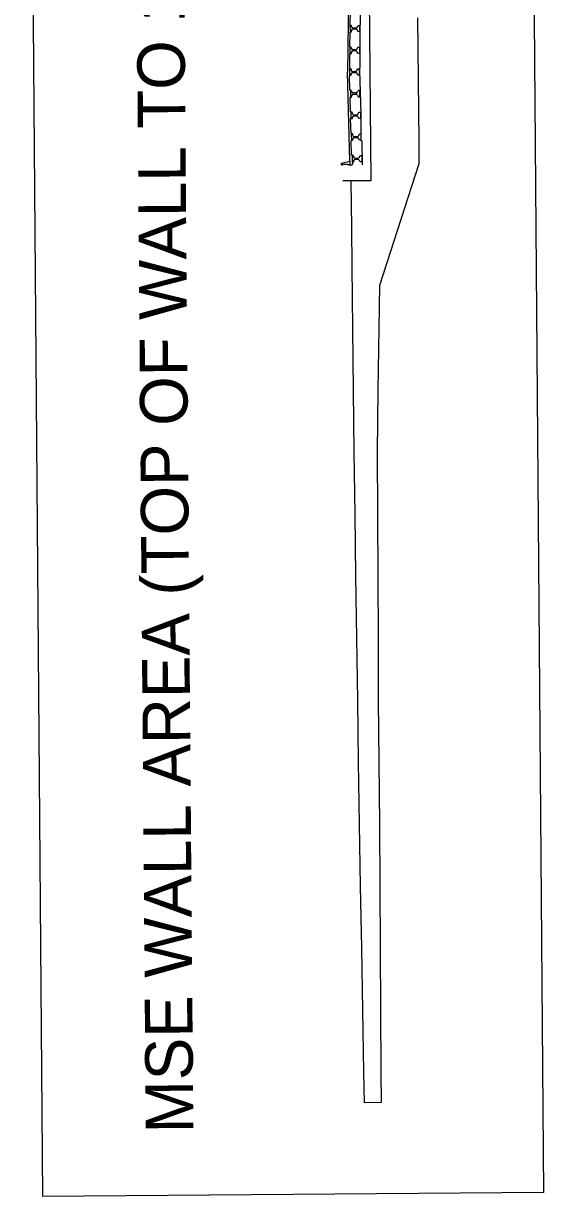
# Model space of a CAD drawing. Extents: x 592274 to 721355, y 141734 to 173089.
# Drawn here: x 594004.6 to 594214.4, y 172097.8 to 172570.9 of the extents above; entities that cross this region are included whole.
import ezdxf

# ---------------------------------------------------------------- set-up
doc = ezdxf.new("R2010")
doc.units = 0
doc.layers.add('B_CONC', color=7, linetype='Continuous')
doc.layers.add('B_SCREEN', color=7, linetype='Continuous')

msp = doc.modelspace()

# ---------------------------------------------------------------- linework, layer by layer
at = {"layer": 'B_CONC'}
for p, q in [((594144.78, 172507.62), (594143.46, 172673.56)), ((594163.48, 172573.14), (594163.78, 172548.14)), ((594163.78, 172548.14), (594164, 172523.14)), ((594164, 172523.14), (594164.07, 172514.3)), ((594164.07, 172514.3), (594148.14, 172465.2)), ((594133.34, 172507.53), (594144.78, 172507.62)), ((594148.14, 172465.2), (594147.88, 172447.97)), ((594147.88, 172447.98), (594147.56, 172422.97)), ((594147.56, 172422.98), (594147.31, 172397.98)), ((594147.31, 172397.98), (594147.39, 172372.99)), ((594147.39, 172373), (594147.58, 172348)), ((594147.58, 172348), (594147.68, 172323)), ((594147.68, 172322.99), (594147.7, 172297.99)), ((594147.7, 172298), (594147.86, 172273)), ((594147.86, 172273.01), (594148.15, 172248.01)), ((594148.15, 172248), (594148.34, 172223)), ((594148.34, 172223), (594148.42, 172198)), ((594148.42, 172198), (594148.57, 172173)), ((594148.57, 172173), (594148.7, 172148)), ((594148.7, 172148.01), (594148.83, 172135.66)), ((594148.83, 172135.66), (594142.16, 172135.61))]:
    msp.add_line(p, q, dxfattribs=at)
msp.add_lwpolyline([(594012.37, 172097.79), (594004.59, 173078.9), (594206.58, 173080.5), (594214.36, 172099.39)], close=True, dxfattribs=at)
for points in [[(594136.89, 172497.92), (594136.8, 172507.56)], [(594136.99, 172488.56), (594136.89, 172497.92)], [(594137.15, 172472.92), (594136.99, 172488.56)], [(594137.42, 172447.92), (594137.15, 172472.92)], [(594137.71, 172422.93), (594137.42, 172447.92)], [(594138.02, 172397.93), (594137.71, 172422.93)], [(594138.34, 172372.93), (594138.02, 172397.93)], [(594138.67, 172347.93), (594138.34, 172372.93)], [(594139.03, 172322.93), (594138.67, 172347.93)], [(594139.39, 172297.93), (594139.03, 172322.93)], [(594139.78, 172272.94), (594139.39, 172297.93)], [(594140.18, 172247.94), (594139.78, 172272.94)], [(594140.59, 172222.94), (594140.18, 172247.94)], [(594141.02, 172197.94), (594140.59, 172222.94)], [(594141.47, 172172.95), (594141.02, 172197.94)], [(594141.93, 172147.95), (594141.47, 172172.95)], [(594142.16, 172135.61), (594141.93, 172147.95)]]:
    msp.add_lwpolyline(points, dxfattribs=at)
at = {"layer": 'B_SCREEN'}
for p, q in [((594135.71, 172587.29), (594135.27, 172551.29)), ((594140.37, 172579.08), (594140.44, 172570.33)), ((594136.32, 172576.13), (594136.25, 172570.21)), ((594136.22, 172567.38), (594136.14, 172561.46)), ((594136.43, 172567.38), (594136.22, 172567.38)), ((594136.43, 172567.38), (594136.24, 172567.38)), ((594136.41, 172570.21), (594136.25, 172570.21)), ((594136.41, 172570.21), (594136.73, 172570.22)), ((594136.41, 172570.21), (594136.73, 172570.22)), ((594136.43, 172567.38), (594136.41, 172570.21)), ((594136.75, 172567.38), (594136.43, 172567.38)), ((594136.75, 172567.38), (594136.43, 172567.38)), ((594136.73, 172570.22), (594136.8, 172569.66)), ((594136.73, 172570.22), (594136.8, 172569.66)), ((594136.81, 172567.94), (594136.75, 172567.38)), ((594136.81, 172567.94), (594136.75, 172567.38)), ((594137.47, 172569.08), (594138.66, 172569.09)), ((594137.47, 172569.08), (594138.66, 172569.09)), ((594138.66, 172568.54), (594137.47, 172568.53)), ((594138.66, 172568.54), (594137.47, 172568.53)), ((594139.26, 172569.47), (594139.53, 172570.07)), ((594139.26, 172569.47), (594139.53, 172570.07)), ((594139.55, 172567.57), (594139.27, 172568.16)), ((594139.55, 172567.57), (594139.27, 172568.16)), ((594139.53, 172570.07), (594140.1, 172570.08)), ((594139.53, 172570.07), (594140.1, 172570.08)), ((594140.12, 172567.58), (594139.55, 172567.57)), ((594140.12, 172567.58), (594139.55, 172567.57)), ((594140.1, 172570.08), (594140.16, 172570.01)), ((594140.1, 172570.08), (594140.16, 172570.01)), ((594140.12, 172567.58), (594140.18, 172567.64)), ((594140.12, 172567.58), (594140.18, 172567.64)), ((594140.16, 172570.01), (594140.18, 172567.64)), ((594140.16, 172570.01), (594140.18, 172567.64)), ((594140.37, 172570.33), (594140.24, 172570.33)), ((594140.44, 172570.33), (594140.24, 172570.33)), ((594140.24, 172570.33), (594140.31, 172561.58)), ((594136.11, 172558.63), (594136.04, 172552.71)), ((594136.39, 172558.63), (594136.11, 172558.63)), ((594136.37, 172561.46), (594136.14, 172561.46)), ((594136.37, 172561.46), (594136.69, 172561.47)), ((594136.37, 172561.46), (594136.69, 172561.47)), ((594136.39, 172558.63), (594136.37, 172561.46)), ((594136.71, 172558.63), (594136.39, 172558.63)), ((594136.71, 172558.63), (594136.39, 172558.63)), ((594136.69, 172561.47), (594136.76, 172560.91)), ((594136.69, 172561.47), (594136.76, 172560.91)), ((594136.77, 172559.19), (594136.71, 172558.63)), ((594136.77, 172559.19), (594136.71, 172558.63)), ((594137.42, 172560.33), (594138.62, 172560.33)), ((594137.42, 172560.33), (594138.62, 172560.33)), ((594138.62, 172559.79), (594137.43, 172559.78)), ((594138.62, 172559.79), (594137.43, 172559.78)), ((594139.22, 172560.72), (594139.49, 172561.32)), ((594139.22, 172560.72), (594139.49, 172561.32)), ((594139.51, 172558.82), (594139.23, 172559.41)), ((594139.51, 172558.82), (594139.23, 172559.41)), ((594139.49, 172561.32), (594140.06, 172561.33)), ((594139.49, 172561.32), (594140.06, 172561.33)), ((594140.08, 172558.83), (594139.51, 172558.82)), ((594140.08, 172558.83), (594139.51, 172558.82)), ((594140.06, 172561.33), (594140.12, 172561.26)), ((594140.06, 172561.33), (594140.12, 172561.26)), ((594140.08, 172558.83), (594140.14, 172558.89)), ((594140.08, 172558.83), (594140.14, 172558.89)), ((594140.12, 172561.26), (594140.14, 172558.89)), ((594140.12, 172561.26), (594140.14, 172558.89)), ((594140.31, 172561.58), (594140.2, 172561.58)), ((594140.2, 172561.58), (594140.27, 172552.83)), ((594136.28, 172515.29), (594135.27, 172551.29)), ((594136.26, 172552.71), (594136.04, 172552.71)), ((594136.23, 172543.99), (594136.06, 172549.88)), ((594136.28, 172549.88), (594136.06, 172549.88)), ((594136.26, 172552.71), (594136.58, 172552.71)), ((594136.28, 172549.88), (594136.26, 172552.71)), ((594136.26, 172552.71), (594136.58, 172552.71)), ((594136.6, 172549.88), (594136.28, 172549.88)), ((594136.6, 172549.88), (594136.28, 172549.88)), ((594136.58, 172552.71), (594136.65, 172552.16)), ((594136.58, 172552.71), (594136.65, 172552.16)), ((594136.67, 172550.44), (594136.6, 172549.88)), ((594136.67, 172550.44), (594136.6, 172549.88)), ((594137.32, 172551.57), (594138.51, 172551.58)), ((594137.32, 172551.57), (594138.51, 172551.58)), ((594138.52, 172551.04), (594137.32, 172551.03)), ((594138.52, 172551.04), (594137.32, 172551.03)), ((594139.11, 172551.97), (594139.39, 172552.57)), ((594139.11, 172551.97), (594139.39, 172552.57)), ((594139.41, 172550.07), (594139.12, 172550.66)), ((594139.41, 172550.07), (594139.12, 172550.66)), ((594139.39, 172552.57), (594139.95, 172552.57)), ((594139.39, 172552.57), (594139.95, 172552.57)), ((594139.97, 172550.07), (594139.41, 172550.07)), ((594139.97, 172550.07), (594139.41, 172550.07)), ((594139.95, 172552.57), (594140.01, 172552.51)), ((594139.95, 172552.57), (594140.01, 172552.51)), ((594139.97, 172550.07), (594140.03, 172550.14)), ((594139.97, 172550.07), (594140.03, 172550.14)), ((594140.01, 172552.51), (594140.03, 172550.14)), ((594140.01, 172552.51), (594140.03, 172550.14)), ((594140.09, 172552.83), (594140.12, 172549.83)), ((594140.27, 172552.83), (594140.09, 172552.83)), ((594140.29, 172549.83), (594140.12, 172549.83)), ((594140.29, 172549.83), (594140.36, 172541.08)), ((594136.5, 172543.99), (594136.23, 172543.99)), ((594136.82, 172544), (594136.5, 172543.99)), ((594136.82, 172544), (594136.5, 172543.99)), ((594136.5, 172543.99), (594136.53, 172541.16)), ((594136.9, 172543.44), (594136.82, 172544)), ((594136.9, 172543.44), (594136.82, 172544)), ((594139.63, 172543.85), (594139.36, 172543.25)), ((594139.63, 172543.85), (594139.36, 172543.25)), ((594140.19, 172543.86), (594139.63, 172543.85)), ((594140.19, 172543.86), (594139.63, 172543.85)), ((594140.19, 172543.86), (594140.26, 172543.79)), ((594140.19, 172543.86), (594140.26, 172543.79)), ((594140.27, 172541.42), (594140.26, 172543.79)), ((594140.27, 172541.42), (594140.26, 172543.79)), ((594136.47, 172535.21), (594136.3, 172541.16)), ((594136.53, 172541.16), (594136.3, 172541.16)), ((594136.53, 172541.16), (594136.85, 172541.16)), ((594136.53, 172541.16), (594136.85, 172541.16)), ((594136.85, 172541.16), (594136.91, 172541.72)), ((594136.85, 172541.16), (594136.91, 172541.72)), ((594138.76, 172542.87), (594137.56, 172542.86)), ((594138.76, 172542.87), (594137.56, 172542.86)), ((594137.57, 172542.31), (594138.76, 172542.32)), ((594137.57, 172542.31), (594138.76, 172542.32)), ((594139.37, 172541.94), (594139.65, 172541.35)), ((594139.37, 172541.94), (594139.65, 172541.35)), ((594139.65, 172541.35), (594140.21, 172541.36)), ((594139.65, 172541.35), (594140.21, 172541.36)), ((594140.21, 172541.36), (594140.27, 172541.42)), ((594140.21, 172541.36), (594140.27, 172541.42)), ((594140.56, 172541.08), (594140.36, 172541.08)), ((594140.56, 172541.08), (594140.63, 172532.33)), ((594136.77, 172535.22), (594136.47, 172535.21)), ((594136.79, 172532.38), (594136.77, 172535.22)), ((594136.77, 172535.22), (594137.09, 172535.22)), ((594136.79, 172532.38), (594136.77, 172535.22)), ((594136.77, 172535.22), (594137.09, 172535.22)), ((594137.09, 172535.22), (594137.16, 172534.66)), ((594137.09, 172535.22), (594137.16, 172534.66)), ((594137.83, 172534.08), (594139.02, 172534.09)), ((594137.83, 172534.08), (594139.02, 172534.09)), ((594139.62, 172534.48), (594139.9, 172535.07)), ((594139.62, 172534.48), (594139.9, 172535.07)), ((594139.9, 172535.07), (594140.46, 172535.08)), ((594139.9, 172535.07), (594140.46, 172535.08)), ((594140.46, 172535.08), (594140.52, 172535.02)), ((594140.46, 172535.08), (594140.52, 172535.02)), ((594140.52, 172535.02), (594140.54, 172532.64)), ((594140.52, 172535.02), (594140.54, 172532.64)), ((594136.71, 172526.46), (594136.55, 172532.38)), ((594136.79, 172532.38), (594136.55, 172532.38)), ((594137.11, 172532.38), (594136.79, 172532.38)), ((594137.11, 172532.38), (594136.79, 172532.38)), ((594137.18, 172532.94), (594137.11, 172532.38)), ((594137.18, 172532.94), (594137.11, 172532.38)), ((594139.03, 172533.55), (594137.83, 172533.54)), ((594139.03, 172533.55), (594137.83, 172533.54)), ((594139.92, 172532.57), (594139.63, 172533.17)), ((594139.92, 172532.57), (594139.63, 172533.17)), ((594140.48, 172532.58), (594139.92, 172532.57)), ((594140.48, 172532.58), (594139.92, 172532.57)), ((594140.48, 172532.58), (594140.54, 172532.64)), ((594140.48, 172532.58), (594140.54, 172532.64)), ((594140.71, 172532.33), (594140.63, 172532.33)), ((594140.74, 172532.33), (594140.63, 172532.33)), ((594140.81, 172523.58), (594140.74, 172532.33)), ((594136.95, 172526.47), (594136.71, 172526.46)), ((594136.95, 172526.47), (594137.27, 172526.47)), ((594136.97, 172523.63), (594136.95, 172526.47)), ((594136.95, 172526.47), (594137.27, 172526.47)), ((594137.27, 172526.47), (594137.34, 172525.91)), ((594137.27, 172526.47), (594137.34, 172525.91)), ((594138.01, 172525.33), (594139.2, 172525.34)), ((594138.01, 172525.33), (594139.2, 172525.34)), ((594139.21, 172524.8), (594138.01, 172524.79)), ((594139.21, 172524.8), (594138.01, 172524.79)), ((594139.8, 172525.73), (594140.08, 172526.32)), ((594139.8, 172525.73), (594140.08, 172526.32)), ((594140.08, 172526.32), (594140.64, 172526.33)), ((594140.08, 172526.32), (594140.64, 172526.33)), ((594140.64, 172526.33), (594140.7, 172526.27)), ((594140.64, 172526.33), (594140.7, 172526.27)), ((594140.7, 172526.27), (594140.72, 172523.89)), ((594140.7, 172526.27), (594140.72, 172523.89)), ((594136.96, 172517.72), (594136.79, 172523.63)), ((594136.97, 172523.63), (594136.79, 172523.63)), ((594137.29, 172523.64), (594136.97, 172523.63)), ((594137.29, 172523.64), (594136.97, 172523.63)), ((594137.36, 172524.19), (594137.29, 172523.64)), ((594137.36, 172524.19), (594137.29, 172523.64)), ((594140.1, 172523.82), (594139.81, 172524.42)), ((594140.1, 172523.82), (594139.81, 172524.42)), ((594140.66, 172523.83), (594140.1, 172523.82)), ((594140.66, 172523.83), (594140.1, 172523.82)), ((594140.66, 172523.83), (594140.72, 172523.89)), ((594140.66, 172523.83), (594140.72, 172523.89)), ((594140.98, 172523.58), (594140.81, 172523.58)), ((594141.09, 172523.58), (594140.81, 172523.58)), ((594141.09, 172523.58), (594141.17, 172513.88)), ((594132.88, 172514.58), (594136.28, 172515.29)), ((594136.28, 172515.07), (594136.27, 172515.05)), ((594136.28, 172515.07), (594136.27, 172515.05)), ((594136.28, 172515.29), (594136.28, 172515.12)), ((594136.28, 172515.29), (594136.28, 172515.12)), ((594136.28, 172515.12), (594136.28, 172515.07)), ((594136.28, 172515.12), (594136.28, 172515.07)), ((594137.3, 172517.72), (594136.96, 172517.72)), ((594137.3, 172517.72), (594137.62, 172517.72)), ((594137.32, 172514.89), (594137.3, 172517.72)), ((594137.3, 172517.72), (594137.62, 172517.72)), ((594137.62, 172517.72), (594137.69, 172517.16)), ((594137.62, 172517.72), (594137.69, 172517.16)), ((594137.71, 172515.45), (594137.64, 172514.89)), ((594137.71, 172515.45), (594137.64, 172514.89)), ((594138.36, 172516.58), (594139.55, 172516.59)), ((594138.36, 172516.58), (594139.55, 172516.59)), ((594139.56, 172516.05), (594138.37, 172516.04)), ((594139.56, 172516.05), (594138.37, 172516.04)), ((594140.15, 172516.98), (594140.43, 172517.58)), ((594140.15, 172516.98), (594140.43, 172517.58)), ((594140.45, 172515.08), (594140.17, 172515.67)), ((594140.45, 172515.08), (594140.17, 172515.67)), ((594140.43, 172517.58), (594140.99, 172517.58)), ((594140.43, 172517.58), (594140.99, 172517.58)), ((594141.01, 172515.08), (594140.45, 172515.08)), ((594141.01, 172515.08), (594140.45, 172515.08)), ((594140.99, 172517.58), (594141.05, 172517.52)), ((594140.99, 172517.58), (594141.05, 172517.52)), ((594141.01, 172515.08), (594141.07, 172515.14)), ((594141.01, 172515.08), (594141.07, 172515.14)), ((594141.05, 172517.52), (594141.07, 172515.14)), ((594141.05, 172517.52), (594141.07, 172515.14)), ((594132.88, 172514.58), (594132.82, 172514.51)), ((594132.82, 172513.88), (594132.82, 172514.51)), ((594132.89, 172513.82), (594132.82, 172513.88)), ((594132.89, 172513.82), (594133.32, 172513.82)), ((594133.32, 172513.82), (594133.45, 172513.95)), ((594135.54, 172513.96), (594133.45, 172513.95)), ((594135.67, 172513.84), (594135.54, 172513.96)), ((594135.67, 172513.84), (594136.27, 172513.85)), ((594136.27, 172515.02), (594136.24, 172514.96)), ((594136.27, 172515.02), (594136.24, 172514.96)), ((594136.24, 172514.96), (594136.25, 172514.89)), ((594136.24, 172514.96), (594136.25, 172514.89)), ((594136.25, 172514.89), (594136.24, 172514.83)), ((594136.25, 172514.89), (594136.24, 172514.83)), ((594136.24, 172514.83), (594136.25, 172514.75)), ((594136.24, 172514.83), (594136.25, 172514.75)), ((594136.25, 172514.75), (594136.25, 172514.68)), ((594136.25, 172514.75), (594136.25, 172514.68)), ((594136.25, 172514.68), (594136.25, 172514.56)), ((594136.25, 172514.68), (594136.25, 172514.56)), ((594136.25, 172514.56), (594136.25, 172514.5)), ((594136.25, 172514.56), (594136.25, 172514.5)), ((594136.25, 172514.5), (594136.25, 172514.41)), ((594136.25, 172514.5), (594136.25, 172514.41)), ((594136.25, 172514.41), (594136.25, 172514.38)), ((594136.25, 172514.41), (594136.25, 172514.38)), ((594136.25, 172514.38), (594136.25, 172514.33)), ((594136.25, 172514.38), (594136.25, 172514.33)), ((594136.25, 172514.33), (594136.27, 172514.26)), ((594136.25, 172514.33), (594136.27, 172514.26)), ((594136.27, 172515.05), (594136.27, 172515.02)), ((594136.27, 172515.05), (594136.27, 172515.02)), ((594136.27, 172514.26), (594136.28, 172514.18)), ((594136.27, 172514.26), (594136.28, 172514.18)), ((594136.33, 172513.91), (594136.27, 172513.85)), ((594136.28, 172514.18), (594136.3, 172514.16)), ((594136.28, 172514.18), (594136.3, 172514.16)), ((594136.3, 172514.16), (594136.33, 172514.12)), ((594136.3, 172514.16), (594136.33, 172514.12)), ((594136.33, 172513.98), (594136.33, 172514.12)), ((594136.33, 172513.98), (594136.33, 172514.12)), ((594136.33, 172514.05), (594136.33, 172513.91)), ((594136.33, 172514.05), (594136.33, 172513.91)), ((594136.4, 172513.85), (594136.33, 172513.91)), ((594136.4, 172513.85), (594137.11, 172513.85)), ((594137.18, 172513.91), (594137.11, 172513.85)), ((594137.24, 172514.25), (594137.18, 172513.91)), ((594137.37, 172514.89), (594137.26, 172514.36)), ((594137.64, 172514.89), (594137.32, 172514.89)), ((594137.64, 172514.89), (594137.32, 172514.89))]:
    msp.add_line(p, q, dxfattribs=at)
msp.add_lwpolyline([(594137.24, 172514.25), (594137.17, 172514.32), (594137.26, 172514.36)], dxfattribs=at)
for centre, start, end in [((594137.46, 172569.74), 187.3266, 270.4539), ((594137.46, 172569.74), 187.3266, 270.4539), ((594137.48, 172567.87), 90.4539, 173.5812), ((594137.48, 172567.87), 90.4539, 173.5812), ((594138.65, 172569.75), 270.4539, 335.3703), ((594138.65, 172569.75), 270.4539, 335.3703), ((594138.67, 172567.88), 25.5375, 90.4539), ((594138.67, 172567.88), 25.5375, 90.4539), ((594137.42, 172560.99), 187.3266, 270.4539), ((594137.42, 172560.99), 187.3266, 270.4539), ((594137.43, 172559.12), 90.4539, 173.5812), ((594137.43, 172559.12), 90.4539, 173.5812), ((594138.61, 172561), 270.4539, 335.3703), ((594138.61, 172561), 270.4539, 335.3703), ((594138.63, 172559.13), 25.5375, 90.4539), ((594138.63, 172559.13), 25.5375, 90.4539), ((594137.31, 172552.24), 187.3266, 270.4539), ((594137.31, 172552.24), 187.3266, 270.4539), ((594137.33, 172550.37), 90.4539, 173.5812), ((594137.33, 172550.37), 90.4539, 173.5812), ((594138.51, 172552.25), 270.4539, 335.3703), ((594138.51, 172552.25), 270.4539, 335.3703), ((594138.52, 172550.37), 25.5375, 90.4539), ((594138.52, 172550.37), 25.5375, 90.4539), ((594137.56, 172543.52), 187.3266, 270.4539), ((594137.56, 172543.52), 187.3266, 270.4539), ((594137.57, 172541.65), 90.4539, 173.5812), ((594137.57, 172541.65), 90.4539, 173.5812), ((594138.75, 172543.53), 270.4539, 335.3703), ((594138.75, 172543.53), 270.4539, 335.3703), ((594138.77, 172541.66), 25.5375, 90.4539), ((594138.77, 172541.66), 25.5375, 90.4539), ((594137.82, 172534.74), 187.3266, 270.4539), ((594137.82, 172534.74), 187.3266, 270.4539), ((594139.02, 172534.75), 270.4539, 335.3703), ((594139.02, 172534.75), 270.4539, 335.3703), ((594137.84, 172532.87), 90.4539, 173.5812), ((594137.84, 172532.87), 90.4539, 173.5812), ((594139.03, 172532.88), 25.5375, 90.4539), ((594139.03, 172532.88), 25.5375, 90.4539), ((594138, 172526), 187.3266, 270.4539), ((594138, 172526), 187.3266, 270.4539), ((594138.02, 172524.12), 90.4539, 173.5812), ((594138.02, 172524.12), 90.4539, 173.5812), ((594139.2, 172526), 270.4539, 335.3703), ((594139.2, 172526), 270.4539, 335.3703), ((594139.21, 172524.13), 25.5375, 90.4539), ((594139.21, 172524.13), 25.5375, 90.4539), ((594138.36, 172517.25), 187.3266, 270.4539), ((594138.36, 172517.25), 187.3266, 270.4539), ((594138.37, 172515.37), 90.4539, 173.5812), ((594138.37, 172515.37), 90.4539, 173.5812), ((594139.55, 172517.26), 270.4539, 335.3703), ((594139.55, 172517.26), 270.4539, 335.3703), ((594139.56, 172515.38), 25.5375, 90.4539), ((594139.56, 172515.38), 25.5375, 90.4539)]:
    msp.add_arc(centre, 0.667, start, end, dxfattribs=at)

# ---------------------------------------------------------------- texts
at = {"layer": 'B_CONC'}
msp.add_text("MSE WALL AREA (TOP OF WALL TO 1.5' BELOW FINISHED GRADE)", height=19.2, rotation=90.4539, dxfattribs=at).set_placement((594073.13, 172123.37))

doc.saveas('drawing.dxf')
